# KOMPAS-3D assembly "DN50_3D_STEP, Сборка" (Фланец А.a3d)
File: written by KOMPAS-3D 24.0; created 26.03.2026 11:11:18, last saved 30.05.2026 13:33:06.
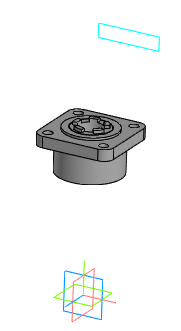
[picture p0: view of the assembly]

Document properties: Автор: R2D2; Полное имя файла: E:\Работа\Зайцев\GVWR2121M-2W-F-ОСТ Задвижка клиновая 30с964нж DN.ru Ду50-300 Ру25\исходные материалы\DN50\Фланец А.a3d

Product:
- Body: Тело 2  | qty 1
    Масса: 2.709631
- Part/product: DN50_3D_STEP  | designation Сборка
    Масса: 2.725126

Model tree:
1. Перпендикулярная плоскость:2
     Координата Z = -90
2. Операция без истории:2
3. Эскиз:1  (with: Грань.Операция без истории:2, Ребро.Операция без истории:2)
4. Элемент выдавливания:1  (with: Грань.Операция без истории:2)
     Расстояние 2 = 14.5
5. Массив по концентрической сетке:1  (with: Элемент выдавливания:1, Грань.Операция без истории:2)  (4 pattern instances)
     Шаг 2 = 360
6. Скругление:1
     Радиус = 13.5
7. Эскиз:2  (with: Грань.Операция без истории:2, Ребро.Операция без истории:2)
8. Элемент выдавливания:2
     Расстояние 2 = 20
9. Эскиз:3  (with: Грань.Операция без истории:2, Ребро.Операция без истории:2)
10. Элемент выдавливания:3  (with: Грань.Операция без истории:2)
     Расстояние 2 = 3
11. Эскиз:4  (with: Грань.Операция без истории:2, Ребро.Операция без истории:2)
12. Элемент выдавливания:4
     Расстояние 1 = 3
13. Эскиз:5  (with: Грань.Операция без истории:2, Ребро.Операция без истории:2)
14. Элемент выдавливания:5
     Расстояние 1 = 1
